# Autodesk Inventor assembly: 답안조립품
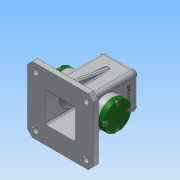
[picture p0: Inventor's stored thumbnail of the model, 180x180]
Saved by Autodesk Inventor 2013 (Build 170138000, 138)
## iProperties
Created: 2016-02
Part Number: 답안조립품
Document SubType Name: Assembly
Designer: Administrator
Author: Administrator
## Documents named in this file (16)
- C:\Users\Administrator\Desktop\460212V1006\답안조립품.iam
- C:\Users\Administrator\Desktop\460212V1006\V벨트풀리.ipt
- C:\Users\Administrator\Desktop\460212V1006\고정핀 1.2 x 10.ipt
- C:\Users\Administrator\Desktop\460212V1006\뒤커버.ipt
- C:\Users\Administrator\Desktop\460212V1006\링크.ipt
- C:\Users\Administrator\Desktop\460212V1006\멈춤나사 M3x8.ipt
- C:\Users\Administrator\Desktop\460212V1006\베어링 12 x 32 x 10.ipt
- C:\Users\Administrator\Desktop\460212V1006\본체.ipt
- C:\Users\Administrator\Desktop\460212V1006\볼트 M4 x 12.ipt
- C:\Users\Administrator\Desktop\460212V1006\부시.ipt
- C:\Users\Administrator\Desktop\460212V1006\슬라이드.ipt
- C:\Users\Administrator\Desktop\460212V1006\앞커버.ipt
- C:\Users\Administrator\Desktop\460212V1006\오일실 12 25 7.ipt
- C:\Users\Administrator\Desktop\460212V1006\키 4 x 4 x 10.ipt
- C:\Users\Administrator\Desktop\460212V1006\편심축.ipt
- C:\Users\Administrator\Desktop\460212V1006\핀 5 x 18.ipt
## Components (11 placed, 4 different names)
1. V벨트풀리:1 — 플러쉬:2
2. 고정핀 1.2 x 10:1 — 각도:1
3. 핀 5 x 18:1 — 각도:2
4. ISO 4762 M4 x 12:2
5. ISO 4762 M4 x 12:3
6. ISO 4762 M4 x 12:4
7. ISO 4762 M4 x 12:5
8. ISO 4762 M4 x 12:1
9. ISO 4762 M4 x 12:6
10. ISO 4762 M4 x 12:7
11. ISO 4762 M4 x 12:8
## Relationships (3: Angle 2, Flush 1)
- 플러쉬:2 [Flush]: V벨트풀리:1
- 각도:1 [Angle]: 고정핀 1.2 x 10:1
- 각도:2 [Angle]: 핀 5 x 18:1
